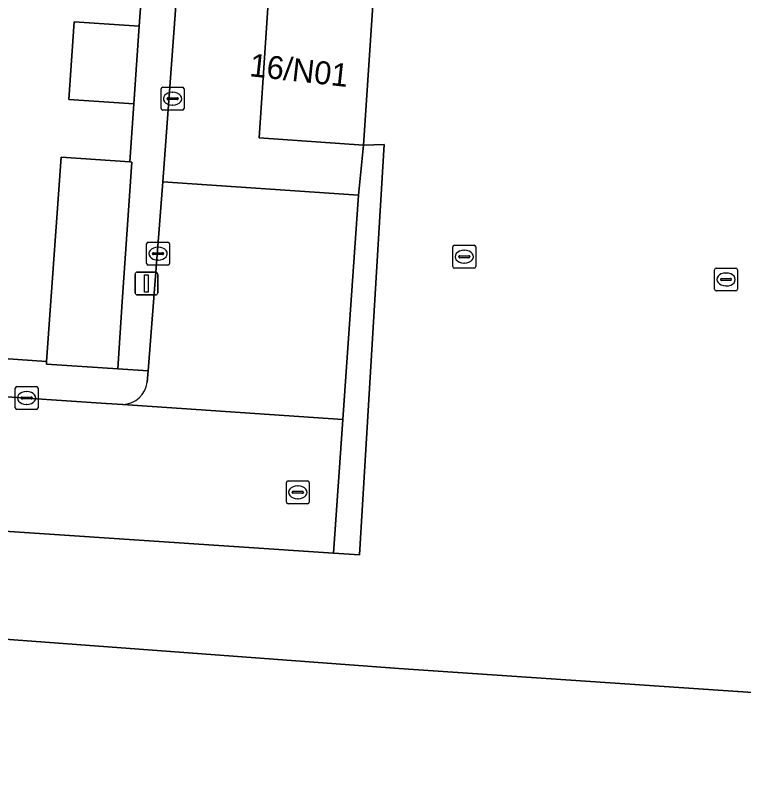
# Model space of a CAD drawing. Extents: x 161848 to 162726, y 385382 to 386521.
# Drawn here: x 162041.47 to 162073.24, y 385671.55 to 385704.61 of the extents above; entities that cross this region are included whole.
import ezdxf

# ---------------------------------------------------------------- set-up
doc = ezdxf.new("R2010")
doc.units = 0
for name, color, linetype in [('IMGEO_Erf', 7, 'Continuous'), ('IMGEO_Hek', 7, 'Continuous'), ('IMGEO_Kolk', 7, 'Continuous'), ('IMGEO_Lichtmast', 7, 'Continuous'), ('IMGEO_Muur', 7, 'Continuous'), ('IMGEO_Pand', 7, 'Continuous'), ('IMGEO_Pand_nummerreeks', 7, 'Continuous'), ('IMGEO_Rijbaan_lokaal_open', 7, 'Continuous'), ('IMGEO_Rioolput', 7, 'Continuous'), ('IMGEO_Terreindeel_open', 7, 'Continuous'), ('IMGEO_Voetpad_open', 7, 'Continuous')]:
    doc.layers.add(name, color=color, linetype=linetype)

msp = doc.modelspace()

# ---------------------------------------------------------------- linework, layer by layer
at = {"layer": 'IMGEO_Erf'}
msp.add_lwpolyline([(162026.232, 385690.631), (162027.726, 385690.519), (162027.721, 385690.258), (162036.352, 385689.938), (162042.835, 385689.5), (162043.472, 385698.403), (162046.468, 385698.203), (162046.644, 385700.731), (162043.801, 385700.928), (162044.036, 385704.32), (162046.879, 385704.122), (162046.958, 385705.335), (162044.772, 385705.477), (162045.086, 385710.314), (162043.96, 385710.389), (162044.347, 385716.364)], dxfattribs=at)
msp.add_lwpolyline([(162103.379, 385708.994), (162108.35, 385708.642), (162117.001, 385708.064), (162117.085, 385709.313), (162057.615, 385713.34), (162056.66, 385698.935), (162057.566, 385698.956), (162056.491, 385681.053), (162055.347, 385681.13), (162038.387, 385682.266), (162038.412, 385682.641), (162036.684, 385682.769), (162034.52, 385682.885), (162034.495, 385682.526), (162034.17, 385677.885), (162058.2, 385676.103), (162110.912, 385672.522), (162111.19, 385677.357), (162106.241, 385677.689), (162101.257, 385678.025)], close=True, dxfattribs=at)
at = {"layer": 'IMGEO_Hek'}
msp.add_lwpolyline([(162056.66, 385698.935), (162057.566, 385698.956), (162056.491, 385681.053)], dxfattribs=at)
at = {"layer": 'IMGEO_Kolk'}
for p, q in [((162047.831, 385700.536), (162047.831, 385701.388)), ((162047.906, 385701.462), (162048.758, 385701.462)), ((162048.832, 385701.388), (162048.832, 385700.536)), ((162048.319, 385701.242), (162048.344, 385701.242)), ((162048.09, 385700.956), (162048.09, 385700.968)), ((162048.528, 385700.919), (162048.13, 385700.919)), ((162048.133, 385701.005), (162048.531, 385701.005)), ((162048.574, 385700.968), (162048.574, 385700.956)), ((162048.758, 385700.462), (162047.906, 385700.462)), ((162048.342, 385700.682), (162048.317, 385700.682)), ((162047.2, 385693.773), (162047.2, 385694.625)), ((162047.275, 385694.699), (162048.127, 385694.699)), ((162047.688, 385694.479), (162047.713, 385694.479)), ((162048.201, 385694.625), (162048.201, 385693.773)), ((162060.552, 385693.639), (162060.552, 385694.491)), ((162060.627, 385694.565), (162061.479, 385694.565)), ((162061.553, 385694.491), (162061.553, 385693.639)), ((162047.459, 385694.193), (162047.459, 385694.205)), ((162047.897, 385694.156), (162047.499, 385694.156)), ((162047.502, 385694.242), (162047.9, 385694.242)), ((162047.943, 385694.205), (162047.943, 385694.193)), ((162060.854, 385694.108), (162061.252, 385694.108)), ((162061.04, 385694.345), (162061.065, 385694.345)), ((162047.711, 385693.919), (162047.686, 385693.919)), ((162060.811, 385694.059), (162060.811, 385694.071)), ((162061.249, 385694.022), (162060.851, 385694.022)), ((162061.063, 385693.785), (162061.038, 385693.785)), ((162061.295, 385694.071), (162061.295, 385694.059)), ((162048.127, 385693.699), (162047.275, 385693.699)), ((162061.479, 385693.565), (162060.627, 385693.565)), ((162071.967, 385692.647), (162071.967, 385693.499)), ((162072.042, 385693.573), (162072.894, 385693.573)), ((162072.968, 385693.499), (162072.968, 385692.647)), ((162072.269, 385693.116), (162072.667, 385693.116)), ((162072.455, 385693.353), (162072.48, 385693.353)), ((162072.226, 385693.067), (162072.226, 385693.079)), ((162072.664, 385693.03), (162072.266, 385693.03)), ((162072.478, 385692.793), (162072.453, 385692.793)), ((162072.71, 385693.079), (162072.71, 385693.067)), ((162072.894, 385692.573), (162072.042, 385692.573)), ((162041.467, 385687.475), (162041.467, 385688.327)), ((162041.542, 385688.401), (162042.394, 385688.401)), ((162041.955, 385688.181), (162041.98, 385688.181)), ((162042.468, 385688.327), (162042.468, 385687.475)), ((162041.726, 385687.895), (162041.726, 385687.907)), ((162042.164, 385687.858), (162041.766, 385687.858)), ((162041.769, 385687.944), (162042.167, 385687.944)), ((162042.21, 385687.907), (162042.21, 385687.895)), ((162041.978, 385687.621), (162041.953, 385687.621)), ((162042.394, 385687.401), (162041.542, 385687.401))]:
    msp.add_line(p, q, dxfattribs=at)
for points in [[(162047.831, 385700.536), (162047.831, 385701.388)], [(162047.906, 385701.462), (162048.758, 385701.462)], [(162048.832, 385701.388), (162048.832, 385700.536)], [(162048.758, 385700.462), (162047.906, 385700.462)], [(162047.2, 385693.773), (162047.2, 385694.625)], [(162047.275, 385694.699), (162048.127, 385694.699)], [(162048.201, 385694.625), (162048.201, 385693.773)], [(162060.552, 385693.639), (162060.552, 385694.491)], [(162060.627, 385694.565), (162061.479, 385694.565)], [(162061.553, 385694.491), (162061.553, 385693.639)], [(162048.127, 385693.699), (162047.275, 385693.699)], [(162061.479, 385693.565), (162060.627, 385693.565)], [(162071.967, 385692.647), (162071.967, 385693.499)], [(162072.042, 385693.573), (162072.894, 385693.573)], [(162072.968, 385693.499), (162072.968, 385692.647)], [(162072.894, 385692.573), (162072.042, 385692.573)], [(162041.467, 385687.475), (162041.467, 385688.327)], [(162041.542, 385688.401), (162042.394, 385688.401)], [(162042.468, 385688.327), (162042.468, 385687.475)], [(162042.394, 385687.401), (162041.542, 385687.401)]]:
    msp.add_lwpolyline(points, dxfattribs=at)
for centre, radius, start, end in [((162047.908, 385701.386), 0.0765, 91.552, 178.448), ((162047.908, 385701.386), 0.0765, 91.552, 178.448), ((162048.756, 385701.386), 0.0765, 1.552, 88.448), ((162048.756, 385701.386), 0.0765, 1.552, 88.448), ((162048.13, 385700.965), 0.0403, 85.8775, 175.7526), ((162048.127, 385700.955), 0.0366, 178.938, 274.7102), ((162048.531, 385700.962), 0.043, 264.8664, 352.4533), ((162048.535, 385700.967), 0.0386, 1.7309, 96.639), ((162047.908, 385700.538), 0.0765, 181.552, 268.448), ((162047.908, 385700.538), 0.0765, 181.552, 268.448), ((162048.756, 385700.538), 0.0765, 271.552, 358.448), ((162048.756, 385700.538), 0.0765, 271.552, 358.448), ((162047.277, 385694.623), 0.0765, 91.552, 178.448), ((162047.277, 385694.623), 0.0765, 91.552, 178.448), ((162048.125, 385694.623), 0.0765, 1.552, 88.448), ((162048.125, 385694.623), 0.0765, 1.552, 88.448), ((162060.629, 385694.489), 0.0765, 91.552, 178.448), ((162060.629, 385694.489), 0.0765, 91.552, 178.448), ((162061.477, 385694.489), 0.0765, 1.552, 88.448), ((162061.477, 385694.489), 0.0765, 1.552, 88.448), ((162047.499, 385694.202), 0.0403, 85.8775, 175.7526), ((162047.496, 385694.192), 0.0366, 178.938, 274.7102), ((162047.9, 385694.199), 0.043, 264.8664, 352.4533), ((162047.904, 385694.204), 0.0386, 1.7309, 96.639), ((162060.851, 385694.068), 0.0403, 85.8775, 175.7526), ((162061.256, 385694.07), 0.0386, 1.7309, 96.639), ((162047.277, 385693.775), 0.0765, 181.552, 268.448), ((162047.277, 385693.775), 0.0765, 181.552, 268.448), ((162048.125, 385693.775), 0.0765, 271.552, 358.448), ((162048.125, 385693.775), 0.0765, 271.552, 358.448), ((162060.848, 385694.058), 0.0366, 178.938, 274.7102), ((162061.252, 385694.065), 0.043, 264.8664, 352.4533), ((162060.629, 385693.641), 0.0765, 181.552, 268.448), ((162060.629, 385693.641), 0.0765, 181.552, 268.448), ((162061.477, 385693.641), 0.0765, 271.552, 358.448), ((162061.477, 385693.641), 0.0765, 271.552, 358.448), ((162072.044, 385693.497), 0.0765, 91.552, 178.448), ((162072.044, 385693.497), 0.0765, 91.552, 178.448), ((162072.892, 385693.497), 0.0765, 1.552, 88.448), ((162072.892, 385693.497), 0.0765, 1.552, 88.448), ((162072.266, 385693.076), 0.0403, 85.8775, 175.7526), ((162072.671, 385693.078), 0.0386, 1.7309, 96.639), ((162072.263, 385693.066), 0.0366, 178.938, 274.7102), ((162072.667, 385693.073), 0.043, 264.8664, 352.4533), ((162072.044, 385692.649), 0.0765, 181.552, 268.448), ((162072.044, 385692.649), 0.0765, 181.552, 268.448), ((162072.892, 385692.649), 0.0765, 271.552, 358.448), ((162072.892, 385692.649), 0.0765, 271.552, 358.448), ((162041.544, 385688.325), 0.0765, 91.552, 178.448), ((162041.544, 385688.325), 0.0765, 91.552, 178.448), ((162042.392, 385688.325), 0.0765, 1.552, 88.448), ((162042.392, 385688.325), 0.0765, 1.552, 88.448), ((162041.766, 385687.904), 0.0403, 85.8775, 175.7526), ((162041.763, 385687.894), 0.0366, 178.938, 274.7102), ((162042.167, 385687.901), 0.043, 264.8664, 352.4533), ((162042.171, 385687.906), 0.0386, 1.7309, 96.639), ((162041.544, 385687.477), 0.0765, 181.552, 268.448), ((162041.544, 385687.477), 0.0765, 181.552, 268.448), ((162042.392, 385687.477), 0.0765, 271.552, 358.448), ((162042.392, 385687.477), 0.0765, 271.552, 358.448)]:
    msp.add_arc(centre, radius, start, end, dxfattribs=at)
for centre, major_axis, ratio, start_param, end_param in [((162048.318, 385700.962), (-0.387, 0.002), 0.722429, 4.712389, 7.853982), ((162048.343, 385700.962), (-0.39, 0.002), 0.717154, 1.570796, 4.712389), ((162047.687, 385694.199), (-0.387, 0.002), 0.722429, 4.712389, 7.853982), ((162047.712, 385694.199), (-0.39, 0.002), 0.717154, 1.570796, 4.712389), ((162061.039, 385694.065), (-0.387, 0.002), 0.722429, 4.712389, 7.853982), ((162061.064, 385694.065), (-0.39, 0.002), 0.717154, 1.570796, 4.712389), ((162072.454, 385693.073), (-0.387, 0.002), 0.722429, 4.712389, 7.853982), ((162072.479, 385693.073), (-0.39, 0.002), 0.717154, 1.570796, 4.712389), ((162041.954, 385687.901), (-0.387, 0.002), 0.722429, 4.712389, 7.853982), ((162041.979, 385687.901), (-0.39, 0.002), 0.717154, 1.570796, 4.712389)]:
    msp.add_ellipse(centre, major_axis=major_axis, ratio=ratio, start_param=start_param, end_param=end_param, dxfattribs=at)
at = {"layer": 'IMGEO_Lichtmast'}
for p, q in [((162046.695, 385692.496), (162046.695, 385693.296)), ((162046.695, 385693.296), (162046.695, 385692.496)), ((162046.795, 385693.396), (162047.585, 385693.396)), ((162047.585, 385693.396), (162046.795, 385693.396)), ((162047.685, 385693.296), (162047.685, 385692.496)), ((162047.685, 385692.496), (162047.685, 385693.296)), ((162047.585, 385692.396), (162046.795, 385692.396)), ((162046.795, 385692.396), (162047.585, 385692.396))]:
    msp.add_line(p, q, dxfattribs=at)
msp.add_lwpolyline([(162047.115, 385693.271), (162047.265, 385693.271), (162047.265, 385692.521), (162047.115, 385692.521), (162047.115, 385693.271)], dxfattribs=at)
for centre, start, end in [((162046.795, 385693.296), 90, 180), ((162046.795, 385693.296), 90, 180), ((162047.585, 385693.296), 0, 90), ((162047.585, 385693.296), 360, 90), ((162046.795, 385692.496), 180, 270), ((162046.795, 385692.496), 180, 270), ((162047.585, 385692.496), 270, 0), ((162047.585, 385692.496), 270, 0)]:
    msp.add_arc(centre, 0.1, start, end, dxfattribs=at)
at = {"layer": 'IMGEO_Muur'}
msp.add_lwpolyline([(162056.491, 385681.053), (162055.347, 385681.13), (162038.387, 385682.266), (162034.495, 385682.526)], dxfattribs=at)
at = {"layer": 'IMGEO_Pand'}
for points in [[(162052.107, 385699.252), (162056.66, 385698.935), (162057.615, 385713.34), (162053.075, 385713.645)], [(162046.879, 385704.122), (162044.036, 385704.32), (162043.801, 385700.928), (162046.644, 385700.731)], [(162046.468, 385698.203), (162043.472, 385698.403), (162042.835, 385689.5), (162042.827, 385689.383), (162045.94, 385689.173), (162046.137, 385692.097), (162046.549, 385698.198)], [(162110.547, 385653.275), (162111.889, 385672.456), (162110.912, 385672.522), (162058.2, 385676.103), (162034.17, 385677.885), (162032.303, 385678.023), (162032.106, 385678.037), (162032.089, 385677.79), (162029.285, 385635.956), (162044.659, 385634.952), (162044.546, 385633.206), (162101.964, 385629.344), (162102.206, 385629.327), (162102.206, 385629.243), (162108.833, 385628.78), (162109.714, 385640.396)]]:
    msp.add_lwpolyline(points, close=True, dxfattribs=at)
at = {"layer": 'IMGEO_Rijbaan_lokaal_open'}
msp.add_lwpolyline([(162053.075, 385713.645), (162049.124, 385713.91), (162047.901, 385697.328), (162056.443, 385696.757), (162056.66, 385698.935), (162052.107, 385699.252)], close=True, dxfattribs=at)
for points in [[(162056.443, 385696.757), (162047.901, 385697.328), (162047.264, 385689.084), (162047.224, 385688.589)], [(162046.169, 385687.615), (162055.757, 385686.967), (162056.443, 385696.757)]]:
    msp.add_lwpolyline(points, dxfattribs=at)
msp.add_arc((162046.122, 385688.725), 1.111, 272.4504, 352.9774, dxfattribs=at)
at = {"layer": 'IMGEO_Rioolput'}
for p, q in [((162053.294, 385683.361), (162053.294, 385684.213)), ((162053.369, 385684.287), (162054.221, 385684.287)), ((162054.295, 385684.213), (162054.295, 385683.361)), ((162053.782, 385684.067), (162053.807, 385684.067)), ((162053.553, 385683.781), (162053.553, 385683.793)), ((162053.991, 385683.744), (162053.593, 385683.744)), ((162053.596, 385683.83), (162053.994, 385683.83)), ((162054.037, 385683.793), (162054.037, 385683.781)), ((162054.221, 385683.287), (162053.369, 385683.287)), ((162053.805, 385683.507), (162053.78, 385683.507))]:
    msp.add_line(p, q, dxfattribs=at)
for points in [[(162053.294, 385683.361), (162053.294, 385684.213)], [(162053.369, 385684.287), (162054.221, 385684.287)], [(162054.295, 385684.213), (162054.295, 385683.361)], [(162054.221, 385683.287), (162053.369, 385683.287)]]:
    msp.add_lwpolyline(points, dxfattribs=at)
for centre, radius, start, end in [((162053.371, 385684.211), 0.0765, 91.552, 178.448), ((162053.371, 385684.211), 0.0765, 91.552, 178.448), ((162054.219, 385684.211), 0.0765, 1.552, 88.448), ((162054.219, 385684.211), 0.0765, 1.552, 88.448), ((162053.593, 385683.79), 0.0403, 85.8775, 175.7526), ((162053.59, 385683.78), 0.0366, 178.938, 274.7102), ((162053.994, 385683.787), 0.043, 264.8664, 352.4533), ((162053.998, 385683.792), 0.0386, 1.7309, 96.639), ((162053.371, 385683.363), 0.0765, 181.552, 268.448), ((162053.371, 385683.363), 0.0765, 181.552, 268.448), ((162054.219, 385683.363), 0.0765, 271.552, 358.448), ((162054.219, 385683.363), 0.0765, 271.552, 358.448)]:
    msp.add_arc(centre, radius, start, end, dxfattribs=at)
for centre, major_axis, ratio, start_param, end_param in [((162053.781, 385683.787), (-0.387, 0.002), 0.722429, 4.712389, 7.853982), ((162053.806, 385683.787), (-0.39, 0.002), 0.717154, 1.570796, 4.712389)]:
    msp.add_ellipse(centre, major_axis=major_axis, ratio=ratio, start_param=start_param, end_param=end_param, dxfattribs=at)
at = {"layer": 'IMGEO_Terreindeel_open'}
msp.add_lwpolyline([(162056.491, 385681.053), (162057.566, 385698.956), (162056.66, 385698.935), (162056.443, 385696.757), (162055.757, 385686.967), (162055.347, 385681.13)], close=True, dxfattribs=at)
at = {"layer": 'IMGEO_Voetpad_open'}
for points in [[(162046.958, 385705.335), (162046.879, 385704.122), (162046.644, 385700.731), (162046.468, 385698.203), (162046.549, 385698.198), (162046.137, 385692.097), (162045.94, 385689.173), (162047.264, 385689.084), (162047.901, 385697.328), (162049.124, 385713.91)], [(162023.994, 385692.934), (162023.749, 385689.119), (162026.661, 385688.935), (162027.604, 385688.858), (162031.577, 385688.596), (162045.435, 385687.665), (162046.169, 385687.615)], [(162042.835, 385689.5), (162036.352, 385689.938), (162027.721, 385690.258), (162027.726, 385690.519), (162026.232, 385690.631)], [(162047.224, 385688.589), (162047.264, 385689.084), (162045.94, 385689.173), (162042.827, 385689.383), (162042.835, 385689.5)]]:
    msp.add_lwpolyline(points, dxfattribs=at)
msp.add_lwpolyline([(162055.757, 385686.967), (162046.169, 385687.615), (162045.435, 385687.665), (162031.577, 385688.596), (162027.604, 385688.858), (162026.917, 385678.403), (162030.981, 385678.056), (162032.106, 385678.037), (162032.303, 385678.023), (162034.17, 385677.885), (162034.495, 385682.526), (162034.52, 385682.885), (162036.684, 385682.769), (162038.412, 385682.641), (162038.387, 385682.266), (162055.347, 385681.13)], close=True, dxfattribs=at)
msp.add_arc((162046.122, 385688.725), 1.111, 272.4504, 352.9774, dxfattribs=at)

# ---------------------------------------------------------------- texts
at = {"layer": 'IMGEO_Pand_nummerreeks'}
msp.add_text('16/N01', height=1, rotation=353.6598, dxfattribs=at).set_placement((162051.656, 385701.946))

doc.saveas('drawing.dxf')
